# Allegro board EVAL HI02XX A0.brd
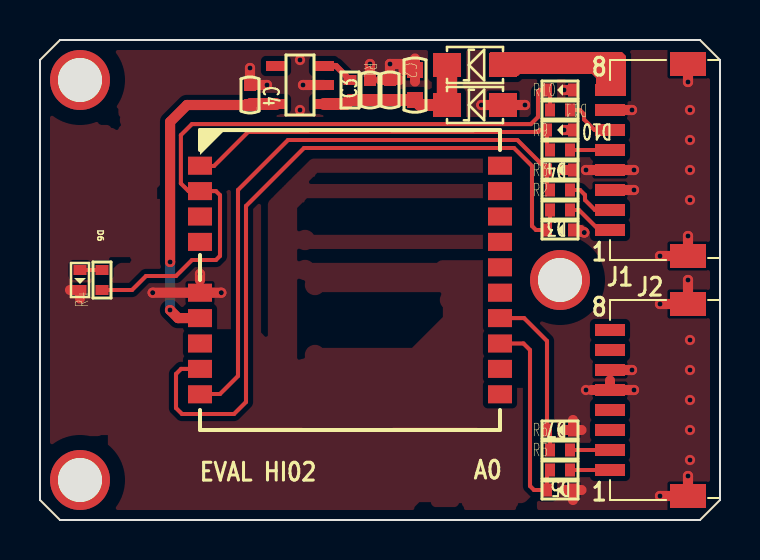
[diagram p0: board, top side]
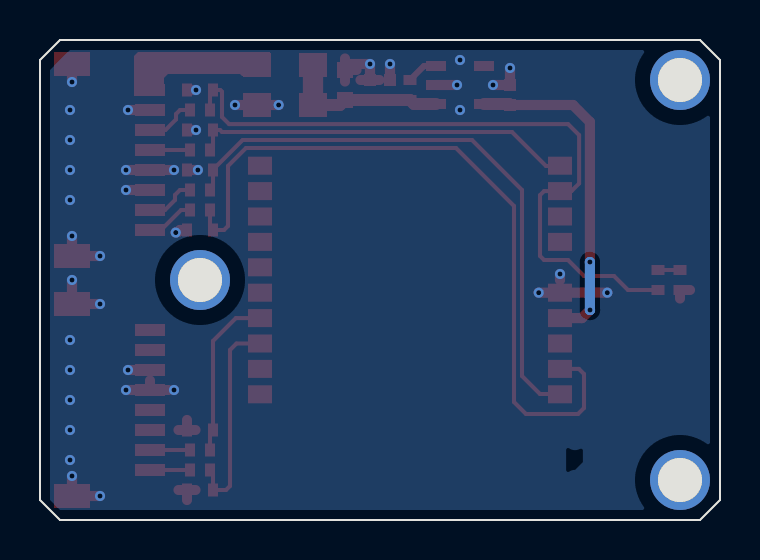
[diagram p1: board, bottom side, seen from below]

Outline 34 x 24 mm; copper layers: TOP, BOTTOM. Coordinates in mm from the lower left corner of the outline.
Outline path: 0,23 0,1 1,0 33,0 34,1 34,23 33,24 1,24 0,23

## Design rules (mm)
constraint set DEFAULT: min track width 0.203

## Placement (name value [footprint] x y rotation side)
C1  10uF  [C0603]  18.75 21.75 270 top
C2  0.1uF  [C0402]  17.5 21.5 270 top
C3  1uF  [C0402]  16.5 21.5 90 top
C4  1uF  [C0402]  10.5 21.25 270 top
D1  1N5819  [SOD123FL]  21.75 22.75 0 top
D2  SDD32A05L01  [SOD123FL]  21.75 20.75 0 top
D3  SBD52C05L01  [SOD-523]  26 14.5 180 top
D4  SBD52C05L01  [SOD-523]  26 17.5 180 top
D5  SBD52C05L01  [SOD-523]  26 1.5 180 top
D6  GREEN  [LED0402]  2 12 270 top
D7  SBD52C05L01  [SOD-523]  26 4.5 180 top
D10  SBD52C05L01  [SOD-523]  26 19.5 180 top
D11  SBD52C05L01  [SOD-523]  26 21.5 180 top
H1  HOLE  [HOLE-2-MM]  2 22 0 top
H2  HOLE  [HOLE-2-MM]  2 2 0 top
H3  HOLE  [HOLE-2-MM]  26 12 0 top
J1  CON10  [5015680807_1]  28.5 18 270 top
J2  CON10  [5015680807_1]  28.5 6 270 top
R1  1K  [R0402]  15.5 21.5 270 top
R2  100R  [R0402]  26 15.5 0 top
R3  100R  [R0402]  26 16.5 0 top
R4  680R  [R0402]  3.1 12 90 top
R5  100R  [R0402]  26 2.5 0 top
R6  100R  [R0402]  26 3.5 0 top
R9  100R  [R0402]  26 18.5 0 top
R10  100R  [R0402]  26 20.5 0 top
U1  SPX3819M5-L-3-3/TR  [SOT23-5-0_95]  13 21.75 90 top
U2  HI02-MI0  [HI02_HI05]  15.5 12 0 top

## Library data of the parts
C1-C4 = Capacity_Nonpolarity
D1 = diode
D2-D5 D7 D10 D11 = DIODE BI-DIR TRIG
D6 = LED
H1-H3 = HOLE
J1 J2 = CON10
R1-R6 R9 R10 = Res
U1 = XC6210
U2 = HI02-MI0

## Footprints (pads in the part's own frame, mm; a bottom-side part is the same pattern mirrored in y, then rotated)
5015680807_1
  rect 0.6x1.5 smd: 1(3.5,0) 2(2.5,0) 3(1.5,0) 4(0.5,0) 5(-0.5,0) 6(-1.5,0) 7(-2.5,0) 8(-3.5,0)
  rect 1.2x1.8 smd: 9(4.8,3.9) 10(-4.8,3.9)
C0402
  rect 0.6x0.6 smd: 1(-0.5,0) 2(0.5,0)
C0603
  rect 0.8x0.8 smd: 1(-0.75,0) 2(0.75,0)
HI02_HI05
  rect 1.2x0.9 smd: 1(-7.5,5.715) 2(-7.5,4.445) 3(-7.5,3.175) 4(-7.5,1.905) 5(-7.5,-0.635) 6(-7.5,-1.905) 7(-7.5,-3.175) 8(-7.5,-4.445) 9(-7.5,-5.715) 10(7.5,-5.715) 11(7.5,-4.445) 12(7.5,-3.175) 13(7.5,-1.905) 14(7.5,-0.635) 15(7.5,0.635) 16(7.5,1.905) 17(7.5,3.175) 18(7.5,4.445) 19(7.5,5.715)
HOLE-2-MM
  round 3 hole 2.2: 1(0,0)
LED0402
  rect 0.5x0.65 smd: 1(-0.5,0) 2(0.5,0)
R0402
  rect 0.5x0.65 smd: 1(-0.5,0) 2(0.5,0)
SOD123FL
  rect 1.4x1.2 smd: 1(1.4,0) 2(-1.4,0)
SOD-523
  rect 0.5x0.65 smd: 1(-0.65,0) 2(0.65,0)
SOT23-5-0_95
  rect 0.5x1 smd: 1(-0.95,-1.2) 2(0,-1.2) 3(0.95,-1.2) 4(0.95,1.2) 5(-0.95,1.2)

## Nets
5V: D1.1(P) J1.8
GND: C1.1 C2.1 C3.2 C4.1 D2.1 D3.1 D4.1 D5.1 D6.2(-) D7.1 D10.1 D11.1 J1.3 J1.4 J1.7 J1.9 J1.10 J2.5 J2.6 J2.9 J2.10 U1.2(VSS) U2.5
VCC: C1.2 C2.2 C3.1 D1.2 D2.2 R1.2 U1.1
DP3V3: C4.2 U1.5 U2.6(VDD)
RST: U2.7
RXD1: D4.2 R3.1 U2.9
RXD2: D7.2 R6.1 U2.13
SIN/PPS: J1.5 R9.2
SOUT: J1.6 R10.2
SYNC_IN/PPS: D10.2 R9.1 U2.1
SYNC_OUT: D11.2 R4.1 R10.1 U2.2
TXD1: D3.2 R2.1 U2.8
TXD2: D5.2 R5.1 U2.12
USART1_RX: J1.2 R3.2
USART1_TX: J1.1 R2.2
USART2_RX: J2.2 R6.2
USART2_TX: J2.1 R5.2
N2198535: D6.1 R4.2
N2224750: R1.1 U1.3

Pads without a net: H1 1; H2 1; H3 1; J2 3 4 7 8; U1 4; U2 3 4 10 11 14 15 16 17 18 19

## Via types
v1: diameter 0.508, hole 0.254, TOP to BOTTOM, 41 vias

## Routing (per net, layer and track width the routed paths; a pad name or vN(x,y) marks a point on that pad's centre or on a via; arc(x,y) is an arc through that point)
GND: length 36.7
  TOP w0.5: D7.1 26.65,5 ; D7.1 26.22,4.5 ; D7.1 27.08,4.5 ; 18.75,21.92 C1.1 ; C1.1 18.17,22.5 ; C1.1 18.75,23.08 ; 2,11.07 D6.2 1.5,11.5 ; 17.98,22 C2.1 17.02,22 ; 28.5,6.98 J2.5 27.57,6.5 ; 26.22,1.5 D5.1 ; D5.1 26.65,1 ; D5.1 27.08,1.5
  TOP w0.508: J1.3 v1(29.7,16.5) ; v1(29.7,17.5) J1.4 v1(27.3,17.5) ; D3.1 27,14.5 27.1,14.4 27.18,14.4 v1(27.21,14.37) ; v1(5.63,11.37) U2.5 v1(9.07,11.37) ; D10.1 v1(26.2,19.5) ; D11.1 v1(26.2,21.5) ; C2.1 v1(17.5,22.8) 18.45,22.8 C1.1 ; v1(24.25,20.75) D2.1 v1(22.07,20.75) ; J2.6 v1(29.6,7.5) ; D4.1 v1(26.11,17.5) ; v1(10.5,22.6) C4.1 v1(11.35,21.75) ; v1(31,13.2) J1.9 v1(32.4,14.2) ; J2.5 v1(29.7,6.5) ; v1(31,10.8) J2.10 v1(32.4,12) ; v1(32.4,2.2) J2.9 v1(31,1.2) ; J1.10 v1(32.4,21.9) ; J1.7 v1(29.6,20.5) ; U1.2 v1(13.15,21.75) ; C3.2 v1(16.5,22.8) ; 8,11.99 v1(8,12.3)
  vias: v1(13,23) v1(13,20.5) v1(27.3,6.5) v1(32.5,20.5) v1(32.5,19) v1(32.5,17.5) v1(32.5,16) v1(32.5,9) v1(32.5,7.5) v1(32.5,6) v1(32.5,4.5) v1(32.5,3)
VCC: length 8.3
  TOP w0.6: U1.1 15.3,20.8 R1.2 C3.1 C2.2 C1.2 19,20.75 D2.2
  TOP w1.016: D1.2 D2.2
DP3V3: length 16.7
  TOP w0.508: C4.2 7.35,20.75 6.51,19.91 v1(6.51,12.9) ; v1(6.5,10.5) 6.9,10.1 U2.6
  TOP w0.6: U1.5 10.55,20.8 C4.2
  BOTTOM w0.508: v1(6.51,12.9) 6.51,10.5 v1(6.5,10.5)
RXD1: length 29.8
  TOP w0.203: R3.1 25.35,16.65 D4.2 25.35,17.52 23.87,19 12.4,19 9.9,16.5 9.9,7.2 9,6.3 8.02,6.3 U2.9
RXD2: length 8.3
  TOP w0.203: U2.13 24.2,10.1 25.35,8.95 D7.2 25.5,4.35 R6.1
SIN/PPS: length 2
  TOP w0.203: J1.5 R9.2
SOUT: length 2.6
  TOP w0.203: R10.2 27,20.5 27.2,20.3 27.2,20.03 27.73,19.5 J1.6
SYNC_IN/PPS: length 19.2
  TOP w0.203: U2.1 8.02,17.7 8.7,17.7 10.4,19.4 24.9,19.4 25,19.5 D10.2 25.35,18.65 R9.1
SYNC_OUT: length 35.3
  TOP w0.203: R10.1 25.5,21.35 D11.2 24.98,21.5 24.9,21.42 24.9,20.15 24.54,19.79 7.59,19.79 7.04,19.24 7.04,16.83 7.43,16.45 U2.2 8.8,16.45 9,16.24 9,13.2 8.8,13 7.6,13 6.8,12.2 5.3,12.2 4.6,11.5 R4.1
TXD1: length 37.4
  TOP w0.203: U2.8 7.05,7.55 6.8,7.3 6.8,5.6 7.1,5.3 9.7,5.3 10.3,5.9 10.3,15.7 13.2,18.6 23.7,18.6 24.6,17.7 24.6,14.7 24.8,14.5 D3.2 25.5,14.65 R2.1
TXD2: length 10.4
  TOP w0.203: R5.1 25.35,2.35 D5.2 24.7,1.5 24.5,1.7 24.5,8.5 24.18,8.82 U2.12
USART1_RX: length 2.6
  TOP w0.203: J1.2 27.75,15.5 27.25,16 27.25,16.25 27,16.5 R3.2
USART1_TX: length 2.4
  TOP w0.203: J1.1 27.95,14.5 26.95,15.5 R2.2
USART2_RX: length 2
  TOP w0.203: R6.2 J2.2
USART2_TX: length 2
  TOP w0.203: J2.1 R5.2
N2198535: length 1.1
  TOP w0.203: D6.1 R4.2
N2224750: length 1.6
  TOP w0.305: U1.3 14.8,22.7 R1.1

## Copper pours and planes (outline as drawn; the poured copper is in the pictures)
5V on TOP (solid shape): 29.3,23.2 29.3,21.2 27.8,21.2 27.8,22.1 27.6,22.3 24,22.3 23.9,22.2 22.5,22.2 22.5,23.4 29.1,23.4
GND on TOP: 1.5,23.5 32.5,23.5 33.5,22.5 33.5,1 33,0.5 1.5,0.5 0.5,1.5 0.5,22.5 ; 21 cut-outs
GND on BOTTOM: 1.5,23.5 32.5,23.5 33.5,22.5 33.5,1 33,0.5 1.5,0.5 0.5,1.5 0.5,22.5 ; 1 cut-out

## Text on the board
Ref Des/Silkscreen Top: EVAL HI02 | A0 | 8 | 1 | J1 | J2
User.8: FIGURE | FINISHED_SIZE | 10.0 | 12.0 | 20.0 | 86.614 | DRILL CHART: TOP to BOTTOM | ALL UNITS ARE IN MILS | PLATED | QTY | 126 | 2 | 3
